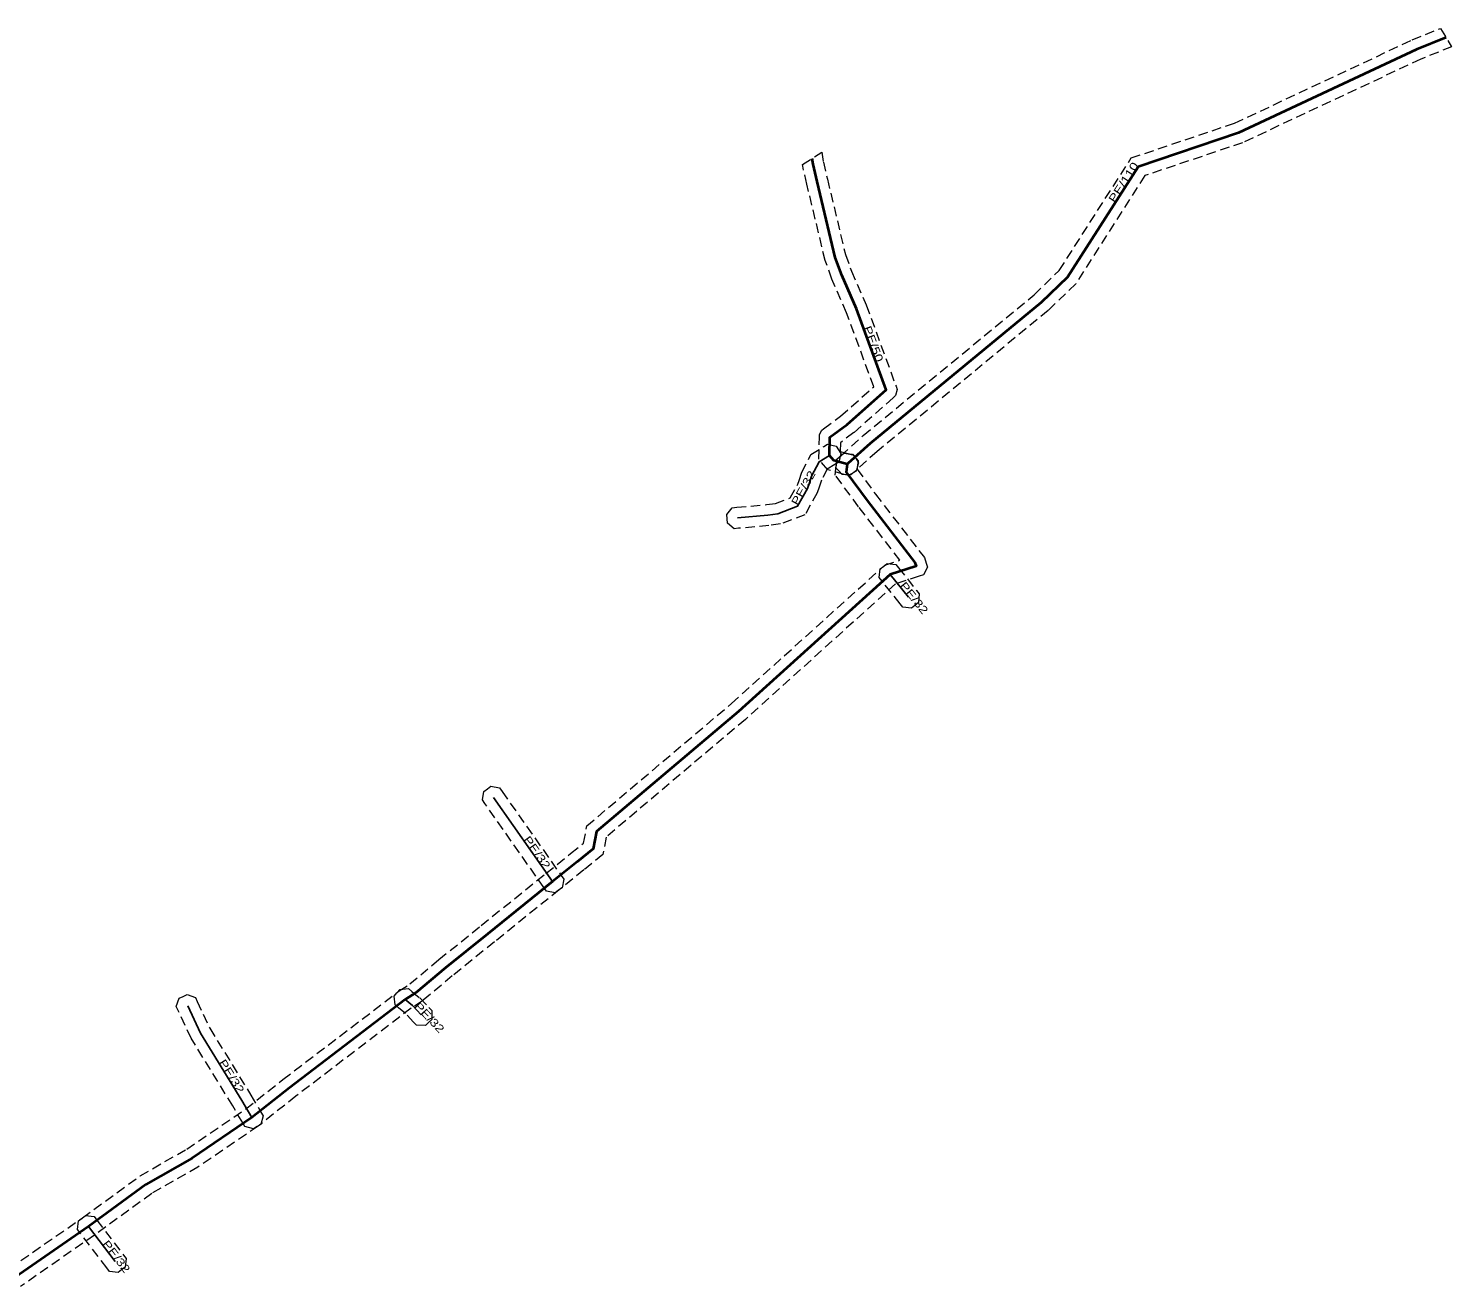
# Model space of a CAD drawing. Extents: x -772780 to -772236, y -1033108 to -1032817.
# Drawn here: x -772371.2 to -772236.3, y -1032936.2 to -1032816.9 of the extents above; entities that cross this region are included whole.
import ezdxf

# ---------------------------------------------------------------- set-up
doc = ezdxf.new("R2010")
doc.units = 0
doc.header["$LTSCALE"] = 0.3
doc.linetypes.add('MEDIUM_DASHED', pattern=[4.5, 3, -1.5])
doc.layers.add('1', color=7, linetype='MEDIUM_DASHED', lineweight=13)
doc.layers.add('24', color=7, linetype='Continuous', lineweight=25)
doc.layers.add('30', color=7, linetype='Continuous')

msp = doc.modelspace()

# ---------------------------------------------------------------- linework, layer by layer
at = {"layer": '1'}
for points in [[(-772239.978, -1032817.994), (-772237.296, -1032816.911), (-772236.251, -1032818.646), (-772239.178, -1032819.828), (-772256.078, -1032827.75), (-772265.326, -1032830.865), (-772271.897, -1032841.127), (-772274.503, -1032843.66), (-772290.739, -1032857.037), (-772292.841, -1032858.918), (-772292.913, -1032858.983), (-772293.22, -1032859.261), (-772294.047, -1032859.22), (-772294.325, -1032858.913), (-772294.603, -1032858.606), (-772294.562, -1032857.779), (-772294.255, -1032857.501), (-772294.179, -1032857.432), (-772292.043, -1032855.519), (-772275.839, -1032842.168), (-772273.457, -1032839.853), (-772266.63, -1032829.195), (-772256.824, -1032825.89)], [(-772297.817, -1032829.827), (-772295.982, -1032828.644), (-772295.83, -1032829.581), (-772295.448, -1032831.209), (-772293.739, -1032838.349), (-772293.161, -1032839.933), (-772291.768, -1032843.138), (-772288.94, -1032850.851), (-772288.834, -1032851.141), (-772288.985, -1032851.739), (-772289.216, -1032851.944), (-772292.934, -1032855.236), (-772294.22, -1032856.2), (-772294.243, -1032857.021), (-772293.316, -1032857.279), (-772292.917, -1032857.39), (-772292.51, -1032858.111), (-772292.621, -1032858.51), (-772292.732, -1032858.909), (-772293.453, -1032859.316), (-772293.852, -1032859.205), (-772295.42, -1032858.768), (-772296.265, -1032857.752), (-772296.206, -1032855.66), (-772296.199, -1032855.432), (-772295.989, -1032855.026), (-772295.806, -1032854.889), (-772294.198, -1032853.684), (-772291.053, -1032850.899), (-772293.626, -1032843.882), (-772295.019, -1032840.675), (-772295.657, -1032838.927), (-772297.394, -1032831.671), (-772297.794, -1032829.969)], [(-772294.378, -1032858.038), (-772294.731, -1032858.255), (-772295.48, -1032858.715), (-772296.017, -1032859.77), (-772296.237, -1032860.434), (-772296.41, -1032860.954), (-772297.581, -1032863.045), (-772299.889, -1032863.91), (-772300.989, -1032864.059), (-772303.872, -1032864.322), (-772304.285, -1032864.36), (-772304.921, -1032863.83), (-772304.959, -1032863.417), (-772304.997, -1032863.004), (-772304.467, -1032862.368), (-772304.054, -1032862.33), (-772301.215, -1032862.071), (-772300.381, -1032861.958), (-772298.969, -1032861.429), (-772298.248, -1032860.142), (-772298.135, -1032859.802), (-772297.867, -1032858.998), (-772297.008, -1032857.307), (-772295.779, -1032856.551), (-772295.426, -1032856.334), (-772294.62, -1032856.526), (-772294.403, -1032856.879), (-772294.186, -1032857.232)], [(-772288.964, -1032867.75), (-772288.706, -1032868.074), (-772286.988, -1032870.226), (-772286.73, -1032870.55), (-772286.822, -1032871.374), (-772287.146, -1032871.632), (-772287.47, -1032871.89), (-772288.294, -1032871.798), (-772288.552, -1032871.474), (-772290.27, -1032869.322), (-772290.528, -1032868.998), (-772290.436, -1032868.174), (-772290.112, -1032867.916), (-772289.788, -1032867.658)], [(-772322.093, -1032898.745), (-772322.331, -1032898.406), (-772327.939, -1032890.426), (-772328.177, -1032890.087), (-772328.035, -1032889.271), (-772327.696, -1032889.033), (-772327.357, -1032888.795), (-772326.541, -1032888.937), (-772326.303, -1032889.276), (-772320.695, -1032897.256), (-772320.457, -1032897.595), (-772320.599, -1032898.411), (-772320.938, -1032898.649), (-772321.277, -1032898.887)], [(-772350.693, -1032921.073), (-772350.903, -1032920.716), (-772351.847, -1032919.105), (-772355.791, -1032912.696), (-772357.032, -1032910.047), (-772357.208, -1032909.672), (-772356.925, -1032908.893), (-772356.55, -1032908.717), (-772356.175, -1032908.541), (-772355.396, -1032908.824), (-772355.22, -1032909.199), (-772354.029, -1032911.744), (-772350.133, -1032918.075), (-772349.177, -1032919.704), (-772348.968, -1032920.061), (-772349.177, -1032920.863), (-772349.534, -1032921.073), (-772349.891, -1032921.282)], [(-772335.188, -1032907.984), (-772334.867, -1032908.246), (-772334.109, -1032908.865), (-772333.246, -1032909.77), (-772332.96, -1032910.07), (-772332.98, -1032910.898), (-772333.28, -1032911.184), (-772333.58, -1032911.47), (-772334.408, -1032911.45), (-772334.694, -1032911.15), (-772335.471, -1032910.335), (-772336.133, -1032909.794), (-772336.454, -1032909.532), (-772336.536, -1032908.708), (-772336.274, -1032908.387), (-772336.012, -1032908.066)], [(-772364.985, -1032929.605), (-772364.734, -1032929.935), (-772362.204, -1032933.265), (-772361.953, -1032933.595), (-772362.065, -1032934.415), (-772362.395, -1032934.666), (-772362.725, -1032934.917), (-772363.545, -1032934.805), (-772363.796, -1032934.475), (-772366.326, -1032931.145), (-772366.577, -1032930.815), (-772366.465, -1032929.995), (-772366.135, -1032929.744), (-772365.805, -1032929.493)]]:
    msp.add_lwpolyline(points, close=True, dxfattribs=at)
for points in [[(-772373.053, -1032934.543), (-772366.11, -1032929.725), (-772360.625, -1032925.729), (-772356.214, -1032923.219), (-772350.633, -1032919.404), (-772347.091, -1032916.608), (-772336.076, -1032908.202), (-772335.058, -1032907.541), (-772332.294, -1032905.23), (-772328.288, -1032901.995), (-772322.14, -1032897.052), (-772319.801, -1032895.172), (-772318.57, -1032894.172), (-772318.267, -1032892.548), (-772304.548, -1032880.937), (-772290, -1032867.813), (-772288.576, -1032867.351), (-772292.486, -1032862.282), (-772294.697, -1032859.273), (-772294.579, -1032858.139), (-772294.536, -1032857.727), (-772293.893, -1032857.204), (-772293.481, -1032857.247), (-772293.069, -1032857.29), (-772292.546, -1032857.933), (-772292.589, -1032858.345), (-772292.627, -1032858.711), (-772290.888, -1032861.08), (-772286.242, -1032867.103)], [(-772286.242, -1032867.103), (-772286.086, -1032867.613), (-772285.967, -1032868.004), (-772286.345, -1032868.729), (-772286.734, -1032868.855), (-772288.976, -1032869.583), (-772303.232, -1032882.443), (-772316.431, -1032893.614), (-772316.738, -1032895.262), (-772318.545, -1032896.728), (-772320.886, -1032898.61), (-772327.034, -1032903.553), (-772331.024, -1032906.776), (-772333.868, -1032909.153), (-772334.924, -1032909.838), (-772345.865, -1032918.188), (-772349.447, -1032921.016), (-772355.154, -1032924.917), (-772359.539, -1032927.411), (-772364.95, -1032931.355), (-772371.991, -1032936.241)]]:
    msp.add_lwpolyline(points, dxfattribs=at)
at = {"layer": '24'}
for p, q in [((-772289.488, -1032868.698), (-772287.77, -1032870.85)), ((-772321.513, -1032897.831), (-772327.121, -1032889.851)), ((-772365.53, -1032930.54), (-772363, -1032933.87))]:
    msp.add_line(p, q, dxfattribs=at)
at = {"layer": '24', "lineweight": 40}
for points in [[(-772236.773, -1032817.779), (-772239.578, -1032818.911), (-772256.451, -1032826.82), (-772265.978, -1032830.03), (-772272.677, -1032840.49), (-772275.171, -1032842.914), (-772291.391, -1032856.278), (-772293.51, -1032858.175), (-772293.584, -1032858.242)], [(-772293.584, -1032858.242), (-772294.851, -1032857.889), (-772295.255, -1032857.403), (-772295.206, -1032855.689), (-772293.566, -1032854.46), (-772289.879, -1032851.195), (-772292.697, -1032843.51), (-772294.09, -1032840.304), (-772294.698, -1032838.638), (-772296.421, -1032831.44), (-772296.811, -1032829.774), (-772296.899, -1032829.235)], [(-772293.584, -1032858.242), (-772293.662, -1032858.992), (-772291.687, -1032861.681), (-772287.145, -1032867.569), (-772287.043, -1032867.904), (-772289.488, -1032868.698), (-772303.89, -1032881.69), (-772317.349, -1032893.081), (-772317.654, -1032894.717), (-772319.173, -1032895.95), (-772321.513, -1032897.831), (-772327.661, -1032902.774), (-772331.659, -1032906.003), (-772334.463, -1032908.347), (-772335.5, -1032909.02), (-772346.478, -1032917.398), (-772350.04, -1032920.21), (-772355.684, -1032924.068), (-772360.082, -1032926.57), (-772365.53, -1032930.54), (-772372.522, -1032935.392)]]:
    msp.add_lwpolyline(points, dxfattribs=at)
at = {"layer": '24'}
for points in [[(-772295.255, -1032857.403), (-772296.244, -1032858.011), (-772296.942, -1032859.384), (-772297.185, -1032860.117), (-772297.329, -1032860.548), (-772298.275, -1032862.237), (-772300.135, -1032862.934), (-772301.102, -1032863.065), (-772303.963, -1032863.326)], [(-772335.5, -1032909.02), (-772334.79, -1032909.599), (-772333.97, -1032910.46)], [(-772350.04, -1032920.21), (-772350.99, -1032918.59), (-772354.91, -1032912.22), (-772356.126, -1032909.623)]]:
    msp.add_lwpolyline(points, dxfattribs=at)

# ---------------------------------------------------------------- texts
at = {"layer": '30', "width": 1.3}
for s, rotation, p in [('PE/110', 57.363, (-772268.202, -1032833.502)), ('PE/50', 290.137, (-772292.044, -1032845.291)), ('PE/32', 60.747, (-772298.268, -1032862.224)), ('PE/32', 308.601, (-772288.629, -1032869.774)), ('PE/32', 305.098, (-772324.317, -1032893.841)), ('PE/32', 313.603, (-772334.696, -1032909.698)), ('PE/32', 301.608, (-772353.209, -1032914.983)), ('PE/32', 307.226, (-772364.265, -1032932.205))]:
    msp.add_text(s, height=0.75, rotation=rotation, dxfattribs=at).set_placement(p)

doc.saveas('drawing.dxf')
